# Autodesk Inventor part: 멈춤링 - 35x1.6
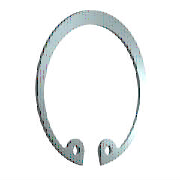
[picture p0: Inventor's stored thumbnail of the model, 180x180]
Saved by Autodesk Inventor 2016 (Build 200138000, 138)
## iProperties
IsCustomPart: 1
Created: 2015-09
Part Number: 멈춤링 - 35x1.6
Material: 강철, 연강
Description: 리테이닝 링(C형)
Document SubType Name: Modeling
Standard: KS B 1336
Designer: mduedu
Standards Organization: KS
Language: ko-KR
Size Designation: 35x1.6
Categories: <MemberInstance><Categories><Category DisplayName="샤프트 부품" InternalName="7f7aeb1f-a693-4053-b835-cee3144e0d98" Mnemonic="SHFT"><Category DisplayName="써클립" Inter
Density: 7.86 g/cm^3
Mass: 3.5371 g
Surface Area: 9.09651 cm^2
Volume: 0.450013 cm^3
Appearance: 광택 - 검은색
Author: mduedu
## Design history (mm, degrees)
sketch "스케치1"
  geometry: L1 (0, 15.113)-(0, -73.177) reference; L2 (-45.5, 0)-(45.5, 0) reference; L3 (-4.964, 1)-(1.502, 1); L4 (0, -2.5)-(-5.307, -2.5); L5 (0, -17.5)-(-8.583, -33.888); L6 (-8.583, -33.888)-(-21.772, -26.981); L7 (-7.377, -31.585)-(-17.631, -26.214); L8 (-5.162, -32.745)-(-6.29, -34.898); L9 (5.162, -32.745)-(6.29, -34.898); C1 r 1.25 at (-7.377, -31.585); C2 r 1.25 at (7.377, -31.585); A1 r 15.875 centre (0, -18.375) between (11.82, -28.972) and (-11.82, -28.972); A2 r 18.5 centre (0, -17.5) between (6.29, -34.898) and (-6.29, -34.898); A3 r 2.5 centre (-7.377, -31.585) between (-5.162, -32.745) and (-8.668, -29.444); A4 r 2.5 centre (-9.959, -27.303) between (-11.82, -28.972) and (-8.668, -29.444); A5 r 2.5 centre (9.959, -27.303) between (8.668, -29.444) and (11.82, -28.972); A6 r 2.5 centre (7.377, -31.585) between (8.668, -29.444) and (5.162, -32.745); 3 further points
  constraints: 15 point on circle, 14 end point, 9 symmetric about line, 8 centre point, 6 tangent, 4 coincident, 4 point on line, 3 perpendicular, 1 parallel, 4 other
  dimensions: "d8" = 0.875 distance of A1.centre L5.start (= 0.25 x SRB1); "d38" = 3.5 distance between parallel lines of L4 L3 (= SRB1); "d39" = 17.5 distance from line of L5.start L2 (= 0.5 x WD); "d43" = 18.5 radius of A2 (= 0.5 x ND); "d45" = 2.6 distance between parallel lines of L7 L6 (= 0.5 x SRB2); "d46" = 2.5 radius of A4 (= SD5); "d47" = 6.29 distance from line of L1 L8.end (= 0.17 x ND); "d48" = 2.5 diameter of C1 (= SD5); "d49" = 2.5 radius of A3 (= SD5)
extrude "본체" new body sketch "스케치1" distance "d2" = 1.6 (= SD); taper "d3" = 0 deg
workaxis "Work Axis1"
workaxis "Work Axis2"
workplane "Work Plane1"
body "Solid1"
other parameters: "WD" = 35 [user parameter; used in 3 equation terms], "SD" = 1.6 [user parameter; used in 1 equation term], "SRB1" = 3.5 [user parameter; used in 2 equation terms], "ND" = 37 [user parameter; used in 2 equation terms], "SRB2" = 5.2 [user parameter; used in 1 equation term], "SD5" = 2.5 [user parameter; used in 3 equation terms], "d50" = 0, "d51" = 0, "d52" = 0, "d53" = 0, "WDMIN" = 34 [user parameter], "SD6" = 37.8 [user parameter], "WDMAX" = 35 (= WD) [user parameter], "NND" = 35 (= WD) [user parameter]
